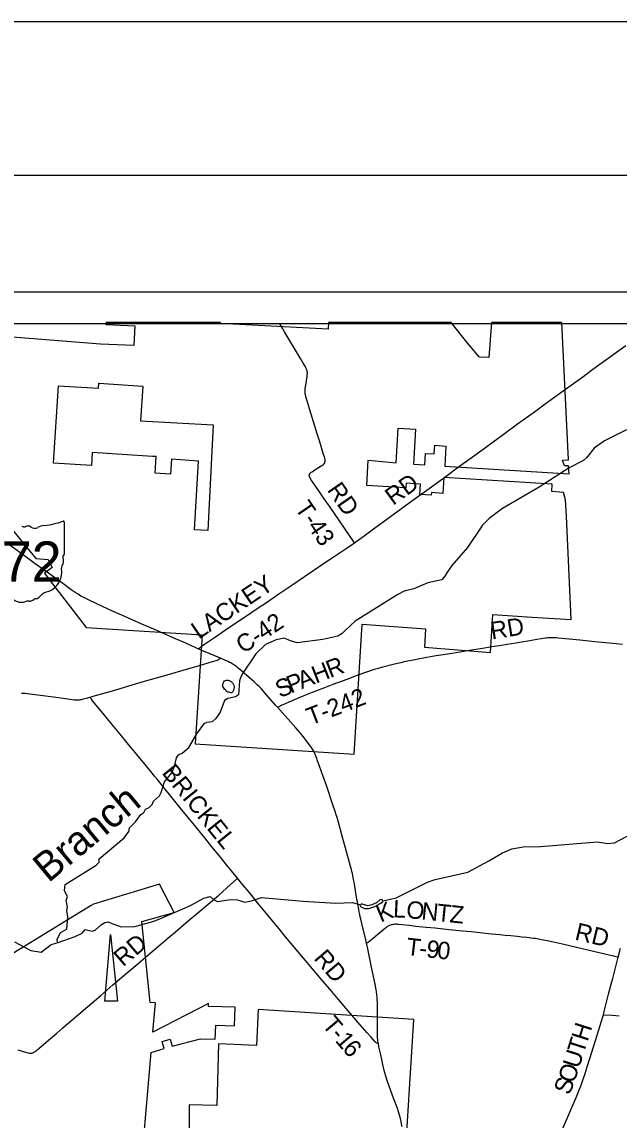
# Model space of a CAD drawing. Extents: x -5.4 to 49.9, y 13.2 to 48.4.
# Drawn here: x 28.171 to 30.118, y 44.845 to 48.429 of the extents above; entities that cross this region are included whole.
import ezdxf

# ---------------------------------------------------------------- set-up
doc = ezdxf.new("R2010")
doc.units = 0
for name, color, linetype in [('GM_X_Corporation', 7, 'Continuous'), ('GM_X_County_Road', 7, 'Continuous'), ('GM_X_County_Road_Text', 7, 'Continuous'), ('GM_X_Minor_Lake', 7, 'Continuous'), ('GM_X_Minor_River', 7, 'Continuous'), ('GM_X_Minor_River_Text', 7, 'Continuous'), ('GM_X_State_Location', 7, 'Continuous'), ('GM_X_State_Route', 7, 'Continuous'), ('GM_X_State_Shield', 7, 'Continuous'), ('GM_X_Township', 7, 'Continuous'), ('GM_X_Township_Road', 7, 'Continuous'), ('GM_X_Township_Road_Text', 7, 'Continuous'), ('SH_Border', 7, 'Continuous'), ('SH_Cut_Line', 7, 'Continuous'), ('SH_Data', 7, 'Continuous')]:
    doc.layers.add(name, color=color, linetype=linetype)

msp = doc.modelspace()

# ---------------------------------------------------------------- linework, layer by layer
at = {"layer": 'GM_X_Corporation'}
for p, q in [((28.8182, 47.4483), (28.4455, 47.4483)), ((29.5706, 47.4483), (29.1706, 47.4483)), ((29.9312, 47.4483), (29.7019, 47.4483))]:
    msp.add_line(p, q, dxfattribs=at)
for points in [[(28.4455, 47.4483), (28.4446, 47.4411), (28.539, 47.4366), (28.5355, 47.3724), (28.4268, 47.3772), (27.8922, 47.4191), (27.8926, 47.4253), (27.7927, 47.4483)], [(28.1146, 46.8031), (28.2164, 46.6772), (28.2566, 46.6747), (28.2696, 46.6483), (28.2442, 46.6293), (28.2597, 46.6087), (28.3804, 46.452), (28.7584, 46.429), (28.7364, 46.0722), (29.2546, 46.0387), (29.2807, 46.4633), (29.4869, 46.4478), (29.4834, 46.3883), (29.6985, 46.3706), (29.7063, 46.4947), (29.8352, 46.4859), (29.9622, 46.4788), (29.9464, 46.816), (29.9432, 46.8688), (29.9372, 46.8931), (29.8985, 46.896), (29.9001, 46.9199), (29.5467, 46.9424), (29.5434, 46.8903), (29.5061, 46.8927), (29.5056, 46.8842), (29.4682, 46.8866), (29.4704, 46.9206), (29.4238, 46.9236), (29.4228, 46.908), (29.2952, 46.9163), (29.3001, 46.9981), (29.3909, 46.9896), (29.3981, 47.1032), (29.4548, 47.0996), (29.4476, 46.986), (29.4852, 46.9836), (29.4872, 47.0205), (29.5155, 47.0187), (29.517, 47.047), (29.5534, 47.0447), (29.5499, 46.9795), (29.9549, 46.9538), (29.9536, 46.9804), (29.9404, 46.9798), (29.9338, 46.9984), (29.9527, 46.9993), (29.9312, 47.4483)], [(29.1706, 47.4483), (29.1693, 47.4265), (28.818, 47.4445), (28.8182, 47.4483)], [(29.7019, 47.4483), (29.6935, 47.3332), (29.6625, 47.3352), (29.6261, 47.3786), (29.5706, 47.4483)], [(28.2903, 47.2416), (28.4207, 47.2334), (28.4217, 47.2496), (28.5648, 47.2401), (28.5574, 47.1268), (28.7946, 47.1135), (28.7768, 46.7687), (28.7338, 46.7715), (28.7471, 46.9958), (28.6586, 47.0019), (28.6552, 46.9525), (28.6059, 46.9558), (28.6086, 47.0103), (28.5971, 47.011), (28.5971, 47.011), (28.5971, 47.0101), (28.4982, 47.0168), (28.4001, 47.0234), (28.3974, 46.9812), (28.274, 46.9892), (28.2903, 47.2416)], [(28.5527, 44.6001), (28.5924, 45.0658), (28.6346, 45.0781), (28.628, 45.101), (28.6544, 45.1086), (28.661, 45.0857), (28.7528, 45.1099), (28.8014, 45.1089), (28.8035, 45.154), (28.8643, 45.1521), (28.8664, 45.2134), (28.7789, 45.2158), (28.7789, 45.2248), (28.598, 45.1311), (28.6061, 45.2272), (28.5891, 45.2284), (28.562, 45.493), (28.6674, 45.5225), (28.6201, 45.6143), (28.4047, 45.5497), (28.3968, 45.5449), (28.1271, 45.3795)], [(28.4599, 45.4501), (28.4825, 45.2333), (28.4415, 45.2333), (28.4599, 45.4501)], [(29.4173, 44.6657), (29.4494, 45.1735), (28.9418, 45.206), (28.9363, 45.0881), (28.8122, 45.094), (28.8061, 44.8928), (28.7167, 44.8942), (28.7171, 44.5971)]]:
    msp.add_lwpolyline(points, dxfattribs=at)
at = {"layer": 'GM_X_County_Road'}
for points in [[(29.255, 46.7289), (29.2646, 46.7357), (29.2867, 46.7519), (29.3127, 46.7711), (29.3289, 46.7829), (29.3563, 46.803), (29.4503, 46.8712), (29.506, 46.9119), (29.5582, 46.95), (29.5859, 46.97), (29.6175, 46.9928), (29.6437, 47.0119), (29.678, 47.037), (29.7079, 47.0589), (29.7406, 47.0827), (29.7873, 47.1167), (29.8419, 47.1567), (29.8725, 47.1791), (29.9083, 47.2048), (29.936, 47.2249), (29.9692, 47.2489), (29.9955, 47.2678), (30.0329, 47.2955), (30.1093, 47.351), (30.1397, 47.3727)], [(28.7479, 46.3822), (28.7502, 46.385), (28.752, 46.387), (28.7531, 46.3882), (28.7548, 46.3898), (28.7565, 46.3911), (28.7586, 46.3927), (28.7617, 46.3951), (28.7662, 46.3981), (28.8023, 46.4223), (28.8352, 46.4447), (28.8557, 46.4587), (28.8902, 46.482), (28.9448, 46.5189), (28.968, 46.5345), (29.0091, 46.5624), (29.0477, 46.5884), (29.0919, 46.6185), (29.1228, 46.6393), (29.1547, 46.661), (29.1891, 46.6844), (29.2253, 46.7086), (29.2484, 46.7242), (29.255, 46.7289)], [(28.393, 46.2251), (28.4029, 46.228), (28.4739, 46.2484), (28.5198, 46.2619), (28.5705, 46.2769), (28.6093, 46.2882), (28.6517, 46.3004), (28.7149, 46.3187), (28.7388, 46.3255), (28.7639, 46.3328), (28.7919, 46.341), (28.8082, 46.346), (28.811, 46.3473), (28.8133, 46.3486), (28.8182, 46.3521)], [(28.1699, 46.2385), (28.1731, 46.2384), (28.1804, 46.2377), (28.2057, 46.2343), (28.2229, 46.2321), (28.2735, 46.2256), (28.3052, 46.2213), (28.3425, 46.2164), (28.3451, 46.2162), (28.3474, 46.2162), (28.3519, 46.2161), (28.3556, 46.2163), (28.3588, 46.2166), (28.3617, 46.2169), (28.3653, 46.2176), (28.3685, 46.2183), (28.3723, 46.2193), (28.3814, 46.2217), (28.393, 46.2251)], [(28.1579, 45.0735), (28.1829, 45.0659), (28.1901, 45.0641), (28.195, 45.0632), (28.1966, 45.063), (28.1985, 45.0628), (28.2001, 45.0628), (28.2013, 45.0629), (28.2024, 45.063), (28.2038, 45.0633), (28.2051, 45.0637), (28.2064, 45.0641), (28.2077, 45.0646), (28.2089, 45.0651), (28.2103, 45.0659), (28.2123, 45.0671), (28.2146, 45.0687), (28.2174, 45.0707), (28.2207, 45.0735), (28.2264, 45.0784), (28.2573, 45.1054), (28.2846, 45.1289), (28.3044, 45.1459), (28.3204, 45.1597), (28.3493, 45.1843), (28.3862, 45.2156), (28.4282, 45.2516), (28.4678, 45.2857), (28.5099, 45.3215), (28.5487, 45.3545), (28.5743, 45.3762), (28.6022, 45.4), (28.6238, 45.4187), (28.647, 45.4384), (28.6717, 45.4592), (28.7133, 45.4947), (28.7447, 45.5211), (28.778, 45.5491), (28.8126, 45.5793), (28.8511, 45.6136), (28.8696, 45.6303), (28.8742, 45.6344)], [(30.0669, 45.1887), (30.0705, 45.2029), (30.0807, 45.2425), (30.084, 45.2554), (30.0883, 45.2718), (30.0925, 45.2879), (30.0973, 45.3071), (30.1061, 45.3419), (30.1139, 45.3724), (30.1151, 45.3767)], [(30.1151, 45.3767), (30.1226, 45.4055)], [(29.9217, 44.7877), (29.9364, 44.8225), (29.9506, 44.8556), (29.9779, 44.9189), (29.9868, 44.9401), (29.994, 44.9586), (30.001, 44.9779), (30.0071, 44.9962), (30.0139, 45.0188), (30.0224, 45.046), (30.0463, 45.1218), (30.0595, 45.1646), (30.0669, 45.1887)], [(30.0669, 45.1887), (30.0967, 45.1867), (30.1188, 45.1854)]]:
    msp.add_lwpolyline(points, dxfattribs=at)
at = {"layer": 'GM_X_Minor_Lake'}
for points in [[(28.8316, 46.251), (28.8249, 46.2621), (28.8257, 46.2651), (28.8261, 46.2674), (28.8273, 46.27), (28.8288, 46.2734), (28.8296, 46.2753), (28.8319, 46.2779), (28.835, 46.2794), (28.8384, 46.2805), (28.8403, 46.2805), (28.8433, 46.2805), (28.8471, 46.2797), (28.8528, 46.2762), (28.8558, 46.2735), (28.8584, 46.2704), (28.8595, 46.2685), (28.8606, 46.2666), (28.8617, 46.2647), (28.8628, 46.2597), (28.8628, 46.2571), (28.8624, 46.254), (28.8616, 46.2502), (28.8608, 46.248), (28.8596, 46.2453), (28.8589, 46.243), (28.8577, 46.2412), (28.855, 46.2397), (28.8531, 46.2389), (28.8471, 46.2409), (28.8425, 46.2417), (28.8399, 46.2429), (28.838, 46.2437), (28.8365, 46.2463), (28.8343, 46.2486), (28.8316, 46.2506), (28.8316, 46.251)], [(29.2749, 45.5416), (29.2876, 45.5349), (29.3024, 45.5354), (29.3219, 45.5419), (29.3387, 45.5514), (29.3483, 45.557), (29.3458, 45.565), (29.3385, 45.5636), (29.3274, 45.5539), (29.3121, 45.5477), (29.2992, 45.5445), (29.292, 45.5462), (29.2807, 45.5494)], [(29.2807, 45.5494), (29.279, 45.55), (29.277, 45.5492), (29.2747, 45.5474), (29.274, 45.5445), (29.2749, 45.5416)]]:
    msp.add_lwpolyline(points, dxfattribs=at)
at = {"layer": 'GM_X_Minor_River'}
for points in [[(30.1427, 47.0978), (30.0704, 47.0615), (30.0367, 47.0382), (30.0122, 47.006), (30.0018, 46.997), (29.9552, 46.9736), (29.8578, 46.9108), (29.738, 46.8412), (29.6946, 46.8086), (29.6733, 46.7865), (29.6235, 46.713), (29.5725, 46.6547), (29.5561, 46.6306), (29.5495, 46.6201), (29.5398, 46.6081), (29.4949, 46.5979), (29.4491, 46.5783), (29.4175, 46.5705), (29.3972, 46.5598), (29.2581, 46.4735), (29.2246, 46.4422), (29.2157, 46.4325), (29.2011, 46.424), (29.1521, 46.4127), (29.0681, 46.4025), (29.047, 46.4089), (29.026, 46.4177), (28.9997, 46.4125), (28.9657, 46.3971), (28.9337, 46.3665), (28.8909, 46.3035), (28.8846, 46.2914), (28.8802, 46.2782), (28.8771, 46.2327), (28.8672, 46.226), (28.8428, 46.2211), (28.8317, 46.2145), (28.8178, 46.1764), (28.8038, 46.1553), (28.7914, 46.1442), (28.7738, 46.1424)], [(28.2866, 45.4235), (28.2855, 45.4337), (28.2972, 45.4571), (28.3178, 45.4674), (28.3207, 45.5076), (28.3173, 45.5286), (28.3201, 45.5396), (28.3151, 45.562), (28.3191, 45.573), (28.3095, 45.5937), (28.3117, 45.6138), (28.4132, 45.6764), (28.4225, 45.6869), (28.4234, 45.6976), (28.5044, 45.7659), (28.5192, 45.7865), (28.5216, 45.799), (28.5416, 45.8177), (28.5583, 45.8422), (28.569, 45.8481), (28.5737, 45.859), (28.586, 45.8645), (28.5952, 45.8743), (28.6003, 45.8852), (28.6196, 45.9035), (28.6254, 45.9137), (28.6358, 45.9489), (28.6594, 45.9782), (28.668, 45.9993), (28.6753, 46.0273), (28.6815, 46.0371), (28.6934, 46.0426), (28.7153, 46.0609), (28.741, 46.1049), (28.7665, 46.1399), (28.7738, 46.1424)], [(29.3473, 45.56), (29.3917, 45.5706), (29.4934, 45.6212), (29.5186, 45.6299), (29.6255, 45.6534), (29.6936, 45.6909), (29.7377, 45.7167), (29.7686, 45.7302), (29.8055, 45.7368), (29.862, 45.738), (30.0475, 45.7533), (30.0804, 45.747), (30.1035, 45.7492), (30.1418, 45.7698), (30.1754, 45.7813), (30.2213, 45.8044), (30.2331, 45.8084), (30.2541, 45.8183), (30.2769, 45.8155)], [(28.1466, 45.4263), (28.1996, 45.3978), (28.2336, 45.3923), (28.2659, 45.4173), (28.2887, 45.4242), (28.3448, 45.4434), (28.3677, 45.4552), (28.3774, 45.4669), (28.3997, 45.4616), (28.4099, 45.4641), (28.4307, 45.4832), (28.441, 45.4895), (28.4517, 45.4916), (28.4619, 45.4873), (28.4951, 45.4757), (28.5391, 45.477), (28.5977, 45.4924), (28.6202, 45.5012), (28.7202, 45.5453), (28.7638, 45.5688)], [(28.7638, 45.5688), (28.7851, 45.5741), (28.7955, 45.5644), (28.8083, 45.5585), (28.8523, 45.5641), (28.8743, 45.5633), (28.8977, 45.5557), (28.9201, 45.5602), (28.9518, 45.5714), (29.088, 45.559), (29.1943, 45.5525), (29.2493, 45.5546), (29.2747, 45.5474)]]:
    msp.add_lwpolyline(points, dxfattribs=at)
at = {"layer": 'GM_X_State_Route'}
for points in [[(29.3829, 44.9162), (29.3827, 44.9165), (29.3685, 44.955), (29.3616, 44.9742), (29.3572, 44.9878), (29.3541, 44.9985), (29.3509, 45.0111), (29.3408, 45.0579), (29.3351, 45.084), (29.3343, 45.0879), (29.3335, 45.0923), (29.3328, 45.0969), (29.3319, 45.1031), (29.3314, 45.108), (29.3309, 45.113), (29.3304, 45.123), (29.3302, 45.1297), (29.3302, 45.1402), (29.3302, 45.1808), (29.33, 45.2299), (29.3298, 45.2369), (29.3295, 45.2416), (29.3292, 45.2472), (29.3285, 45.2533), (29.3281, 45.2571), (29.3276, 45.2607), (29.3269, 45.2655), (29.3261, 45.2699), (29.3224, 45.2888), (29.3111, 45.3442), (29.2988, 45.4038), (29.2947, 45.4218), (29.2908, 45.4389), (29.2827, 45.4727), (29.2762, 45.5), (29.2744, 45.508), (29.2725, 45.5162), (29.2709, 45.5241), (29.2692, 45.5328), (29.2659, 45.5505), (29.2621, 45.5726), (29.2562, 45.6081), (29.254, 45.6208), (29.2524, 45.6302), (29.2512, 45.6365), (29.2499, 45.6423), (29.2484, 45.6493), (29.2467, 45.6562), (29.2451, 45.6627), (29.2434, 45.6688), (29.2356, 45.697), (29.2279, 45.7251), (29.2144, 45.7762), (29.2046, 45.8128), (29.2014, 45.8243), (29.2001, 45.8285), (29.1989, 45.8326), (29.1961, 45.8415), (29.1927, 45.8518), (29.1853, 45.8737), (29.1636, 45.9366), (29.152, 45.9696), (29.1412, 46.0003), (29.1341, 46.0206), (29.1325, 46.0252), (29.1307, 46.0299), (29.129, 46.0338), (29.1274, 46.0375), (29.1256, 46.0413), (29.1234, 46.0461), (29.1204, 46.0518), (29.1181, 46.0558), (29.1153, 46.0602), (29.1113, 46.0662), (29.0928, 46.0911), (29.0792, 46.1079), (29.0644, 46.1251), (29.021, 46.1734), (29.0039, 46.1925), (28.9978, 46.1994), (28.9688, 46.2326), (28.9507, 46.253), (28.9456, 46.2585), (28.9385, 46.2654), (28.928, 46.275), (28.913, 46.2881), (28.8883, 46.3098), (28.8759, 46.3201), (28.8718, 46.3235), (28.8681, 46.3262), (28.8642, 46.329), (28.86, 46.3318), (28.8557, 46.3345), (28.852, 46.3366), (28.8482, 46.3387), (28.8438, 46.3409), (28.8348, 46.345), (28.8182, 46.3521), (28.763, 46.3757), (28.7479, 46.3822), (28.7356, 46.3875), (28.705, 46.4011), (28.672, 46.4157), (28.6008, 46.4467), (28.5621, 46.4637), (28.4972, 46.4922), (28.4689, 46.5049), (28.4339, 46.5211), (28.3907, 46.5415), (28.3733, 46.5498), (28.3635, 46.5551), (28.3539, 46.5607), (28.3451, 46.5664), (28.3319, 46.5758), (28.3043, 46.5959), (28.2428, 46.6402), (28.2283, 46.6509), (28.2147, 46.6607), (28.1759, 46.6887), (28.1286, 46.723)], [(29.4107, 44.8223), (29.4101, 44.8261), (29.4075, 44.8402), (29.4055, 44.8494), (29.4025, 44.8608), (29.4001, 44.8686), (29.3942, 44.8856), (29.3829, 44.9162)]]:
    msp.add_lwpolyline(points, dxfattribs=at)
at = {"layer": 'GM_X_State_Shield'}
for p, q in [((28.3093, 46.6913), (28.3093, 46.7959)), ((28.3092, 46.6913), (28.3093, 46.6913))]:
    msp.add_line(p, q, dxfattribs=at)
for centre, radius, start, end in [((28.1778, 46.789), 0.00855, 219.7921, 297.1024), ((28.1903, 46.7659), 0.0178, 54.4667, 119.1411), ((28.2132, 46.7976), 0.0214, 233.8562, 294.8282), ((28.251, 46.7299), 0.0563, 97.3462, 120.7689), ((28.2153, 47.0638), 0.2796, 275.8445, 288.9065), ((28.3063, 46.7964), 0.00294, 351.8621, 97.738), ((28.3086, 46.6836), 0.00454, 107.944, 210.337), ((28.2797, 46.6703), 0.0273, 340.033, 23.6496), ((28.3061, 46.6908), 0.00314, 289.6038, 7.7341), ((28.231, 46.6341), 0.0699, 292.3089, 8.9858), ((28.3198, 46.6474), 0.0198, 136.8065, 186.9296), ((28.2605, 46.5312), 0.0383, 94.4031, 142.5768), ((28.1691, 46.5749), 0.0401, 230.7004, 286.2918), ((28.1923, 46.5057), 0.0329, 85.6951, 111.2099), ((28.1952, 46.5599), 0.0214, 268.777, 315.5493), ((28.2145, 46.5405), 0.00601, 65.7517, 132.6484), ((28.212, 46.568), 0.0226, 282.8732, 323.2771)]:
    msp.add_arc(centre, radius, start, end, dxfattribs=at)
at = {"layer": 'GM_X_Township'}
msp.add_lwpolyline([(33.0771, 44.431), (33.0771, 47.4437), (28.0105, 47.4437)], dxfattribs=at)
at = {"layer": 'GM_X_Township_Road'}
for points in [[(29.255, 46.7289), (29.2507, 46.7351), (29.2409, 46.7494), (29.1734, 46.8486), (29.1569, 46.8726), (29.1393, 46.8982), (29.1242, 46.9203), (29.1199, 46.9264), (29.1167, 46.9309), (29.1133, 46.936), (29.1118, 46.9384), (29.1106, 46.9404), (29.1098, 46.9419), (29.1092, 46.9433), (29.1088, 46.9444), (29.1086, 46.9453), (29.1084, 46.9464), (29.1082, 46.9476), (29.1081, 46.9489), (29.1081, 46.9501), (29.1083, 46.9514), (29.1086, 46.9525), (29.1088, 46.9531), (29.1091, 46.9537), (29.1093, 46.9542), (29.1097, 46.9549), (29.1103, 46.9556), (29.111, 46.9564), (29.1118, 46.9571), (29.1131, 46.9582), (29.1146, 46.9594), (29.1169, 46.961), (29.1257, 46.9668), (29.1433, 46.9779), (29.1521, 46.9836), (29.1538, 46.9848), (29.1552, 46.9861), (29.1561, 46.987), (29.1568, 46.9879), (29.1575, 46.989), (29.1582, 46.9901), (29.1587, 46.9913), (29.159, 46.9926), (29.1593, 46.9938), (29.1595, 46.9949), (29.1596, 46.9961), (29.1597, 46.9975), (29.1596, 46.9989), (29.1594, 47.0005), (29.159, 47.0028), (29.1587, 47.0042), (29.1584, 47.0053), (29.1572, 47.0097), (29.1548, 47.0174), (29.149, 47.0358), (29.141, 47.0612), (29.1337, 47.0849), (29.1143, 47.1485), (29.1057, 47.1765), (29.0999, 47.1954), (29.0971, 47.205), (29.0964, 47.2078), (29.0958, 47.2103), (29.0952, 47.2133), (29.0948, 47.2162), (29.0945, 47.2191), (29.0945, 47.2222), (29.0945, 47.2253), (29.0948, 47.229), (29.0951, 47.2325), (29.0964, 47.2437), (29.1007, 47.2715), (29.1012, 47.2754), (29.1015, 47.2783), (29.1017, 47.2806), (29.1017, 47.2829), (29.1017, 47.2843), (29.1015, 47.2855), (29.1012, 47.2875), (29.101, 47.2891), (29.1006, 47.2905), (29.1002, 47.292), (29.0998, 47.2934), (29.0992, 47.295), (29.0987, 47.2961), (29.0966, 47.3003), (29.0942, 47.3049), (29.0878, 47.3156), (29.0792, 47.3299), (29.0465, 47.385), (29.0274, 47.4177), (29.0217, 47.4273), (29.0121, 47.4437)], [(29.0039, 46.1925), (29.0093, 46.1951), (29.0192, 46.1996), (29.0282, 46.2037), (29.0442, 46.2106), (29.051, 46.2136), (29.0596, 46.2173), (29.067, 46.2203), (29.0733, 46.2229), (29.0912, 46.23), (29.1024, 46.2346), (29.1298, 46.2456), (29.159, 46.257), (29.1855, 46.2674), (29.2162, 46.2788), (29.231, 46.2843), (29.2565, 46.2937), (29.2673, 46.2976), (29.2861, 46.3043), (29.3084, 46.312), (29.3173, 46.3148), (29.3251, 46.3173), (29.3333, 46.3198), (29.3476, 46.3239), (29.3819, 46.3327), (29.3952, 46.3359), (29.4067, 46.3384), (29.4122, 46.3397), (29.4175, 46.3409), (29.4237, 46.3422), (29.4523, 46.3478), (29.4628, 46.3499), (29.5085, 46.3586), (29.5213, 46.3608), (29.5447, 46.3646), (29.5661, 46.3679), (29.5931, 46.3724), (29.6244, 46.3773), (29.6434, 46.3803), (29.6667, 46.3842), (29.6796, 46.3863), (29.7035, 46.3902), (29.7287, 46.3942), (29.7532, 46.3981), (29.7814, 46.4027), (29.8004, 46.4059), (29.8267, 46.4103), (29.8501, 46.414), (29.8782, 46.4184), (29.882, 46.4189), (29.8854, 46.4194), (29.8882, 46.4196), (29.8906, 46.4198), (29.8929, 46.4199), (29.8963, 46.4199), (29.9, 46.4199), (29.9045, 46.4198), (29.9093, 46.4196), (29.9145, 46.4193), (29.9204, 46.4189), (29.9557, 46.4155), (29.9897, 46.4122), (30.0392, 46.4072), (30.1084, 46.4003), (30.1288, 46.3983)], [(28.8742, 45.6344), (28.8543, 45.6587), (28.8385, 45.6778), (28.8184, 45.7024), (28.7907, 45.7367), (28.7671, 45.7655), (28.7388, 45.8002), (28.7128, 45.8327), (28.6875, 45.8642), (28.6609, 45.897), (28.6339, 45.9304), (28.6124, 45.9571), (28.6038, 45.9674), (28.5915, 45.9823), (28.5772, 45.9995), (28.5457, 46.038), (28.524, 46.0644), (28.5146, 46.0759), (28.4909, 46.1047), (28.464, 46.1373), (28.4304, 46.1781), (28.4016, 46.2132), (28.3978, 46.2181), (28.3961, 46.2206), (28.393, 46.2251)], [(29.3335, 45.0923), (29.3299, 45.0944), (29.3266, 45.0965), (29.3239, 45.0988), (29.3087, 45.116), (29.2969, 45.1297), (29.2663, 45.1648), (29.2282, 45.209), (29.2032, 45.2384), (29.1814, 45.264), (29.1478, 45.3039), (29.0887, 45.3735), (29.0598, 45.4077), (29.0307, 45.4425), (29.0093, 45.4684), (28.9877, 45.4949), (28.9577, 45.5321), (28.9395, 45.5541), (28.9246, 45.5724), (28.9117, 45.5884), (28.8917, 45.6129), (28.8742, 45.6344)], [(29.2947, 45.4218), (29.3006, 45.4264), (29.3171, 45.4393), (29.3317, 45.4511), (29.351, 45.4677), (29.3568, 45.4725), (29.3593, 45.4745), (29.3619, 45.4763), (29.3644, 45.478), (29.3662, 45.479), (29.3687, 45.4802), (29.3711, 45.4812), (29.3736, 45.4822), (29.3762, 45.4829), (29.3776, 45.4833), (29.3789, 45.4835), (29.3814, 45.484), (29.3835, 45.4843), (29.386, 45.4845), (29.3887, 45.4847), (29.3915, 45.4848), (29.3947, 45.4846), (29.3987, 45.4844), (29.4109, 45.4833), (29.4339, 45.4804), (29.4549, 45.4781), (29.4895, 45.4748), (29.5189, 45.4719), (29.563, 45.4672), (29.5748, 45.466), (29.6076, 45.4628), (29.636, 45.4598), (29.6644, 45.4567), (29.702, 45.4528), (29.715, 45.4515), (29.7298, 45.4502), (29.7471, 45.4485), (29.7651, 45.4468), (29.7855, 45.4448), (29.8009, 45.4432), (29.8176, 45.4414), (29.825, 45.4406), (29.8306, 45.4399), (29.8393, 45.4388), (29.8443, 45.4381), (29.8503, 45.4371), (29.8566, 45.436), (29.8656, 45.4343), (29.8834, 45.4307), (29.904, 45.4263), (29.9337, 45.4198), (29.9792, 45.4093), (30.0167, 45.4007), (30.0391, 45.3954), (30.0998, 45.3805), (30.1077, 45.3785), (30.1151, 45.3767)]]:
    msp.add_lwpolyline(points, dxfattribs=at)
at = {"layer": 'SH_Border'}
msp.add_lwpolyline([(4.2889, 47.9288), (36.2889, 47.9288), (36.2889, 26.9288), (4.2889, 26.9288)], close=True, dxfattribs=at)
at = {"layer": 'SH_Cut_Line'}
msp.add_lwpolyline([(2.7889, 26.4288), (36.7889, 26.4288), (36.7889, 48.4288), (2.7889, 48.4288)], close=True, dxfattribs=at)
at = {"layer": 'SH_Data'}
msp.add_line((26.1653, 47.5483), (33.1653, 47.5483), dxfattribs=at)

# ---------------------------------------------------------------- texts
at = {"layer": 'GM_X_County_Road_Text'}
for s, height, rotation, p in [('RD', 0.05682, 35.5957, (29.3812, 46.8491)), ('LACKEY', 0.05682, 34.0161, (28.7476, 46.4128)), ('C-42', 0.05682, 33.7852, (28.8929, 46.3653)), ('RD', 0.05682, 40.4942, (28.5006, 45.343)), ('H', 0.0568, 72.4106, (30.0153, 45.0987)), ('T', 0.0568, 72.4159, (30.0024, 45.0581)), ('U', 0.0568, 72.4, (29.9873, 45.0105)), ('O', 0.0568, 71.4026, (29.971, 44.9621)), ('S', 0.0568, 68.6203, (29.956, 44.9235))]:
    msp.add_text(s, height=height, rotation=rotation, dxfattribs=at).set_placement(p)
at = {"layer": 'GM_X_Minor_River_Text'}
msp.add_text('Branch', height=0.09473, rotation=39.7867, dxfattribs=at).set_placement((28.2573, 45.6171))
at = {"layer": 'GM_X_State_Location'}
for s in ['s', 'r']:
    msp.add_text(s, height=0.000189, dxfattribs=at).set_placement((28.1744, 46.6742))
at = {"layer": 'GM_X_State_Shield'}
msp.add_text('72', height=0.13184, dxfattribs=at).set_placement((28.1045, 46.6015))
at = {"layer": 'GM_X_Township_Road_Text'}
for s, height, rotation, p in [('RD', 0.05682, 304.6339, (29.1644, 46.9015)), ('T-43', 0.05682, 304.4715, (29.0592, 46.8416)), ('RD', 0.05682, 9.1413, (29.7034, 46.413)), ('R', 0.0568, 21.2267, (29.1759, 46.2869)), ('A', 0.0568, 21.2792, (29.0827, 46.2507)), ('H', 0.0568, 21.2352, (29.1293, 46.2688)), ('S', 0.0568, 23.4675, (29.0126, 46.2213)), ('P', 0.0568, 21.917, (29.0473, 46.2364)), ('T-242', 0.05682, 21.1128, (29.1124, 46.1326)), ('BRICKEL', 0.05682, 309.0295, (28.6251, 45.9774)), ('K', 0.0568, 22.0003, (29.3404, 45.4889)), ('L', 0.0568, 357.4449, (29.3805, 45.5066)), ('O', 0.0568, 354.2166, (29.4221, 45.5047)), ('N', 0.0568, 354.1615, (29.4718, 45.4997)), ('T', 0.0568, 354.1612, (29.5215, 45.4946)), ('Z', 0.0568, 354.1652, (29.5638, 45.4903)), ('RD', 0.05682, 346.6748, (29.9711, 45.4343)), ('T', 0.0568, 353.4199, (29.4221, 45.3838)), ('9', 0.0568, 353.5527, (29.4877, 45.3763)), ('0', 0.0568, 354.0633, (29.523, 45.3723)), ('RD', 0.05682, 310.4385, (29.1204, 45.3713)), ('-', 0.0568, 353.4457, (29.4644, 45.3789)), ('T', 0.0568, 310.1853, (29.1472, 45.154)), ('-', 0.0568, 310.2341, (29.1747, 45.1215)), ('1', 0.0568, 310.5134, (29.19, 45.1034)), ('6', 0.0568, 311.5545, (29.2134, 45.076))]:
    msp.add_text(s, height=height, rotation=rotation, dxfattribs=at).set_placement(p)

doc.saveas('drawing.dxf')
